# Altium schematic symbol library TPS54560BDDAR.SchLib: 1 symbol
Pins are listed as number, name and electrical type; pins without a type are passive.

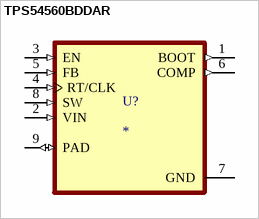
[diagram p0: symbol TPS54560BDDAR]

## TPS54560BDDAR
designator U?
4.5-V to 60-V input, 5-A, step-down DC-DC converter with Eco-modeâ„¢; MF: Texas Instruments; MP: TPS54560BDDAR
footprint VREG_LM5017MR/NOPB
pins: 1 BOOT (out), 2 VIN (in), 3 EN (in), 4 RT/CLK (in), 5 FB (in), 6 COMP (out), 7 GND (power), 8 SW (in), 9 PAD (io)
